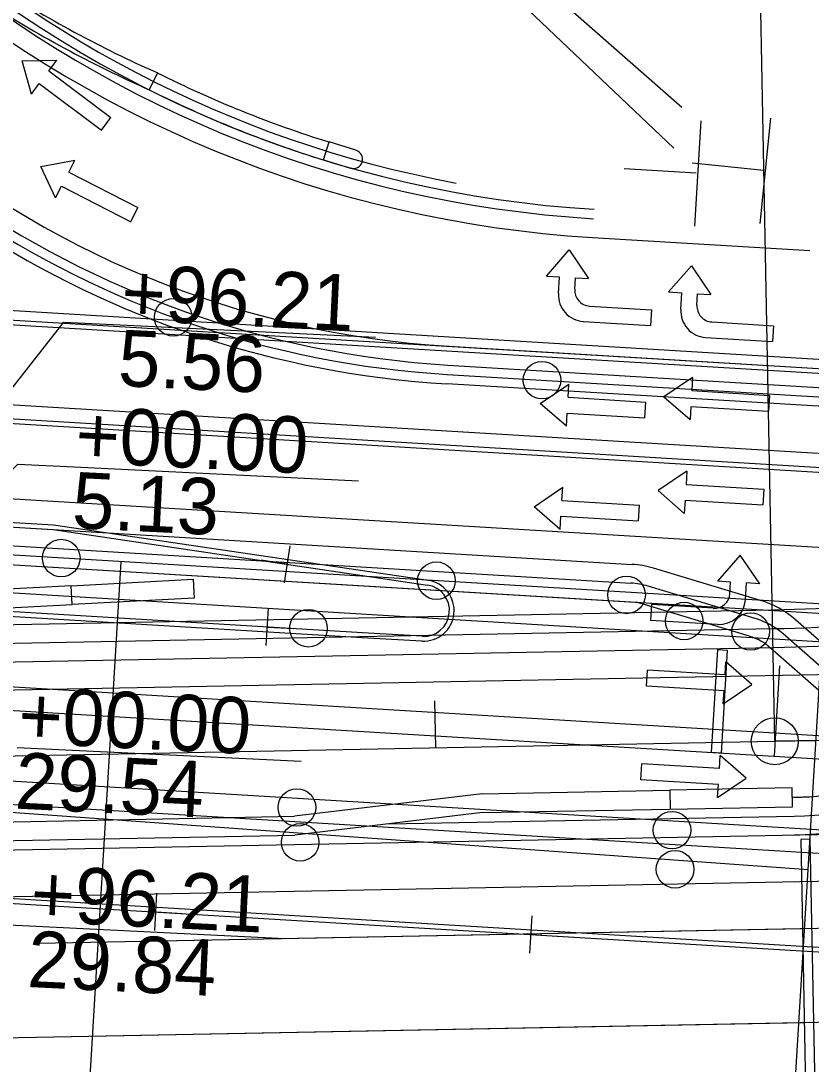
# Model space of a CAD drawing. Extents: x 659657 to 668193, y 633084 to 648639.
# Drawn here: x 662595.7 to 662679.8, y 642371.9 to 642483 of the extents above; entities that cross this region are included whole.
import ezdxf

# ---------------------------------------------------------------- set-up
doc = ezdxf.new("R2010")
doc.units = 0
for name, color, linetype in [('R_Draft', 7, 'Continuous'), ('R_MOT_Stage 1', 7, 'Continuous'), ('R_MOT_Stage 1_Striping', 7, 'Continuous'), ('R_MOT_Stage 1B', 7, 'Continuous'), ('R_MOT_Stage 1B_Striping', 7, 'Continuous'), ('R_MOT_Stage 2', 7, 'Continuous'), ('R_MOT_Stage 2_Striping', 7, 'Continuous'), ('R_MOT_Stage 3', 7, 'Continuous'), ('R_MOT_Stage 3_Striping', 7, 'Continuous'), ('R_MOT_Stage 4', 7, 'Continuous'), ('R_MOT_STAGE 4_ALG', 7, 'Continuous'), ('R_MOT_Stage 4_Striping', 7, 'Continuous'), ('R_MOT_Stage 5', 7, 'Continuous'), ('R_MOT_Stage 5_Striping', 7, 'Continuous'), ('R_MOT_Stage 5_Striping_PPM', 7, 'Continuous'), ('T_SIGNAL CONTROL CABINET', 7, 'Continuous'), ('TEMP_DETECTION ZONE_Stage 2', 7, 'Continuous'), ('TEMP_SIGNAL_HEAD_STAGE 2', 7, 'Continuous'), ('TEXT_TEMP_SIGNAL_POLES_STAGE 2', 7, 'Continuous')]:
    doc.layers.add(name, color=color, linetype=linetype)

msp = doc.modelspace()

# ---------------------------------------------------------------- linework, layer by layer
for p, q in [((662606.31, 642450.61), (662633.48, 642449.29)), ((662601.41, 642435.46), (662631.66, 642433.99)), ((662472.14, 642402.33), (662675.98, 642406.25)), ((662595.34, 642405.58), (662625.58, 642404.12)), ((662596.66, 642386.58), (662623.83, 642385.26))]:
    msp.add_line(p, q)
for points in [[(662577.3, 642421.56), (662600.32, 642450.9), (662606.31, 642450.61)], [(662581.11, 642421.76), (662595.42, 642435.75), (662601.41, 642435.46)], [(662575.84, 642397.32), (662590.67, 642386.87), (662596.66, 642386.58)]]:
    msp.add_lwpolyline(points)
msp.add_arc((662690.63, 641644.39), 762, 88.24549, 91.10143)
at = {"layer": 'R_Draft'}
for p, q in [((662607.84, 642523.97), (662665.24, 642469.4)), ((662675.54, 642472.59), (662674.4, 642461.4)), ((662674.81, 642467.04), (662667.17, 642467.82))]:
    msp.add_line(p, q, dxfattribs=at)
at = {"layer": 'R_MOT_Stage 1'}
for centre in [(662625.46, 642395.49), (662665.36, 642392.62)]:
    msp.add_circle(centre, 2, dxfattribs=at)
at = {"layer": 'R_MOT_Stage 1_Striping'}
msp.add_lwpolyline([(662365.81, 642413.1), (662545.74, 642402.23), (662679.56, 642392.6)], dxfattribs=at)
at = {"layer": 'R_MOT_Stage 1B'}
for p, q in [((662609.4, 642475.63), (662610.3, 642477.42)), ((662627.93, 642468.17), (662628.53, 642470.08)), ((662631.39, 642469.19), (662628.53, 642470.08)), ((662627.93, 642468.17), (662630.8, 642467.28))]:
    msp.add_line(p, q, dxfattribs=at)
for centre, radius, start, end in [((662664.1, 642584.68), 121, 191.5452, 259.5087), ((662664.1, 642584.68), 123, 191.5452, 266.5452), ((662658.88, 642587.86), 120.65, 236.8623, 246.2551), ((662658.88, 642587.86), 122.65, 236.8152, 246.208), ((662664.1, 642584.68), 120, 243.3636, 252.7563), ((662664.1, 642584.68), 122, 243.3636, 252.7564), ((662631.1, 642468.23), 1, 252.7573, 72.7573)]:
    msp.add_arc(centre, radius, start, end, dxfattribs=at)
at = {"layer": 'R_MOT_Stage 1B_Striping'}
msp.add_line((662656.57, 642459.91), (662679.72, 642458.51), dxfattribs=at)
msp.add_arc((662664.1, 642584.68), 125, 191.5452, 266.5452, dxfattribs=at)
at = {"layer": 'R_MOT_Stage 2'}
for centre in [(662625.12, 642399.2), (662665.04, 642396.79)]:
    msp.add_circle(centre, 2, dxfattribs=at)
at = {"layer": 'R_MOT_Stage 2_Striping'}
for p, q in [((662564.68, 642453.94), (662717.74, 642444.7)), ((662586.38, 642442.61), (662717.14, 642434.71)), ((662585.77, 642432.63), (662697.57, 642425.88)), ((662585.17, 642422.65), (662696.97, 642415.9)), ((662584.57, 642412.66), (662696.36, 642405.91))]:
    msp.add_line(p, q, dxfattribs=at)
msp.add_lwpolyline([(662544.65, 642404.55), (662583.97, 642402.68), (662695.76, 642395.93)], dxfattribs=at)
at = {"layer": 'R_MOT_Stage 3'}
for p, q in [((662532.02, 642430.86), (662660.67, 642423.1)), ((662531.97, 642428.86), (662661.25, 642421.06)), ((662673.88, 642419.34), (662662.5, 642422.77)), ((662673.3, 642417.43), (662661.25, 642421.06)), ((662694.99, 642401.73), (662676.86, 642417.69)), ((662691.12, 642402.46), (662675.54, 642416.18)), ((662644.83, 642400.65), (662624.87, 642398.26)), ((662644.83, 642400.65), (662664.82, 642401.03)), ((662497.17, 642395.81), (662624.87, 642398.26)), ((662644.86, 642398.65), (662624.91, 642396.26)), ((662634.88, 642397.46), (662678.04, 642398.28)), ((662644.86, 642398.65), (662664.86, 642399.03)), ((662497.13, 642393.81), (662624.91, 642396.26))]:
    msp.add_line(p, q, dxfattribs=at)
msp.add_lwpolyline([(662664.86, 642399.03), (662677.86, 642399.28), (662677.82, 642401.28), (662664.82, 642401.03)], close=True, dxfattribs=at)
for centre in [(662600.03, 642425.76), (662639.96, 642423.35), (662660.2, 642421.84), (662673.41, 642417.94)]:
    msp.add_circle(centre, 2, dxfattribs=at)
for centre, radius, start, end in [((662660.19, 642415.11), 8, 73.2256, 86.5452), ((662671.57, 642411.68), 8, 48.6396, 73.2256), ((662671.57, 642411.68), 6, 48.6396, 73.2256), ((662677.12, 642446.28), 46, 271.1014, 287.7285), ((662677.12, 642446.28), 48, 271.1014, 291.8551)]:
    msp.add_arc(centre, radius, start, end, dxfattribs=at)
at = {"layer": 'R_MOT_Stage 3_Striping'}
for p, q in [((662582.93, 642451.83), (662717.68, 642443.7)), ((662582.26, 642440.85), (662852.85, 642424.52)), ((662581.6, 642429.87), (662660.79, 642425.09)), ((662674.46, 642421.26), (662663.08, 642424.69)), ((662696.31, 642403.23), (662678.18, 642419.19)), ((662471.94, 642392.32), (662695.17, 642396.61)), ((662597.59, 642384.74), (662695.36, 642386.62)), ((662597.39, 642374.73), (662695.55, 642376.62))]:
    msp.add_line(p, q, dxfattribs=at)
for centre, radius, start, end in [((662660.19, 642415.11), 10, 73.2256, 86.5452), ((662671.57, 642411.68), 10, 48.6396, 73.2256), ((662677.12, 642446.28), 50, 271.1014, 291.8551), ((662582.74, 643136.59), 762, 266.54523, 271.10143)]:
    msp.add_arc(centre, radius, start, end, dxfattribs=at)
at = {"layer": 'R_MOT_Stage 4'}
for p, q in [((662641.18, 642446.31), (662707.9, 642442.29)), ((662707.78, 642440.29), (662641.06, 642444.32)), ((662541.55, 642417.66), (662675.77, 642420.25)), ((662479.84, 642414.48), (662675.81, 642418.25))]:
    msp.add_line(p, q, dxfattribs=at)
for points in [[(662480.71, 642414.45), (662601.2, 642420.82), (662601.1, 642422.81), (662480.61, 642416.45)], [(662601.2, 642420.82), (662601.1, 642422.81), (662614.08, 642423.5), (662614.18, 642421.5)]]:
    msp.add_lwpolyline(points, close=True, dxfattribs=at)
for centre in [(662611.95, 642451.4), (662651.2, 642444.71), (662666.33, 642419.06), (662626.34, 642418.29)]:
    msp.add_circle(centre, 2, dxfattribs=at)
for centre, radius, start, end in [((662647.33, 642548.13), 102, 202.9101, 266.5452), ((662647.33, 642548.13), 104, 207.4876, 266.5452), ((662672, 642616.21), 196, 271.1014, 281.9222), ((662672, 642616.21), 198, 271.1014, 281.9222)]:
    msp.add_arc(centre, radius, start, end, dxfattribs=at)
at = {"layer": 'R_MOT_STAGE 4_ALG'}
for p, q in [((662472.14, 642402.33), (662675.98, 642406.25)), ((662675.98, 642406.25), (662694.97, 642406.61))]:
    msp.add_line(p, q, dxfattribs=at)
for points in [[(662675.98, 642406.25), (662672.14, 642606.21)], [(662639.75, 642410.55), (662639.85, 642405.55)]]:
    msp.add_lwpolyline(points, dxfattribs=at)
msp.add_circle((662675.98, 642406.25), 2.5, dxfattribs=at)
msp.add_arc((662690.63, 641644.39), 762, 88.24549, 91.10143, dxfattribs=at)
at = {"layer": 'R_MOT_Stage 4_Striping'}
for p, q in [((662641.3, 642448.31), (662708.02, 642444.28)), ((662472.35, 642412.33), (662675.84, 642416.25)), ((662472.14, 642402.33), (662675.98, 642406.25)), ((662471.94, 642392.32), (662695.17, 642396.61)), ((662679.75, 642395.82), (662678.75, 642395.8)), ((662678.75, 642395.8), (662679.32, 642366.3)), ((662680.32, 642366.33), (662679.75, 642395.82)), ((662597.59, 642384.74), (662678.94, 642386.3)), ((662597.39, 642374.73), (662679.13, 642376.3))]:
    msp.add_line(p, q, dxfattribs=at)
for centre, radius, start, end in [((662647.33, 642548.13), 100, 191.5452, 266.5452), ((662672, 642616.21), 200, 271.1014, 281.9222), ((662690.63, 641644.39), 762, 88.24549, 91.10143), ((662582.74, 643136.59), 762, 266.54523, 271.10143)]:
    msp.add_arc(centre, radius, start, end, dxfattribs=at)
at = {"layer": 'R_MOT_Stage 5'}
for p, q in [((662624.35, 642427.07), (662623.77, 642423.14)), ((662624, 642425.12), (662621.32, 642425.52)), ((662621.85, 642416.44), (662622.09, 642420.42)), ((662622.03, 642418.42), (662624.74, 642418.25)), ((662609.98, 642386.1), (662610.22, 642390.08)), ((662610.16, 642388.08), (662612.87, 642387.91)), ((662649.91, 642383.69), (662650.15, 642387.67)), ((662650.09, 642385.67), (662652.8, 642385.5))]:
    msp.add_line(p, q, dxfattribs=at)
at = {"layer": 'R_MOT_Stage 5_Striping'}
for p, q in [((661919.1, 642491.41), (662682.71, 642445.31)), ((661918.5, 642481.43), (662682.11, 642435.33)), ((662431.9, 642439.41), (662599.22, 642429.31)), ((662599.22, 642429.31), (662639.08, 642423.39)), ((662523.51, 642423.86), (662632.67, 642417.27)), ((662632.67, 642417.27), (662638.4, 642416.93)), ((662520.53, 642414.02), (662705.2, 642402.88)), ((662410.13, 642410.67), (662704.6, 642392.89)), ((662409.53, 642400.69), (662713.96, 642382.31))]:
    msp.add_line(p, q, dxfattribs=at)
msp.add_lwpolyline([(662670.92, 642415.97), (662670.26, 642404.99), (662669.26, 642405.05), (662669.93, 642416.03)], close=True, dxfattribs=at)
msp.add_arc((662638.6, 642420.17), 3.25, 266.5452, 81.5452, dxfattribs=at)
at = {"layer": 'R_MOT_Stage 5_Striping_PPM'}
for radius, end in [(238.73, 86.5452), (253.73, 62.8692)]:
    msp.add_arc((662357.6, 642147.63), radius, 156.1234, end, dxfattribs=at)
at = {"layer": 'T_SIGNAL CONTROL CABINET'}
for p, q in [((662595.86, 642478.73), (662599.55, 642478.78)), ((662595.86, 642478.73), (662599.55, 642478.78)), ((662596.85, 642475.18), (662595.86, 642478.73)), ((662596.85, 642475.18), (662595.86, 642478.73)), ((662598.7, 642477.65), (662599.55, 642478.78)), ((662598.7, 642477.65), (662599.55, 642478.78)), ((662598.7, 642477.65), (662605.32, 642472.68)), ((662598.7, 642477.65), (662605.32, 642472.68)), ((662596.85, 642475.18), (662597.69, 642476.3)), ((662596.85, 642475.18), (662597.69, 642476.3)), ((662597.69, 642476.3), (662604.3, 642471.33)), ((662597.69, 642476.3), (662604.3, 642471.33)), ((662604.3, 642471.33), (662605.32, 642472.68)), ((662604.3, 642471.33), (662605.32, 642472.68)), ((662678.22, 642370.94), (662684.25, 642470.76)), ((662597.85, 642467.45), (662601.48, 642468.12)), ((662599.42, 642464.11), (662597.85, 642467.45)), ((662600.83, 642466.87), (662601.48, 642468.12)), ((662600.83, 642466.87), (662608.19, 642463.08)), ((662599.42, 642464.11), (662600.06, 642465.37)), ((662600.06, 642465.37), (662607.42, 642461.58)), ((662607.42, 642461.58), (662608.19, 642463.08)), ((662651.67, 642455.79), (662654.09, 642458.57)), ((662654.09, 642458.57), (662656.16, 642455.52)), ((662664.68, 642454.1), (662667.1, 642456.88)), ((662667.1, 642456.88), (662669.17, 642453.83)), ((662651.67, 642455.79), (662653.07, 642455.71)), ((662652.96, 642453.93), (662653.07, 642455.71)), ((662654.68, 642454.39), (662654.76, 642455.61)), ((662654.76, 642455.61), (662656.16, 642455.52)), ((662664.68, 642454.1), (662666.08, 642454.01)), ((662665.97, 642452.24), (662666.08, 642454.01)), ((662667.69, 642452.7), (662667.77, 642453.91)), ((662667.77, 642453.91), (662669.17, 642453.83)), ((662656.26, 642452.6), (662662.84, 642452.21)), ((662662.84, 642452.21), (662662.74, 642450.52)), ((662655.6, 642450.95), (662662.74, 642450.52)), ((662669.28, 642450.91), (662675.85, 642450.51)), ((662675.85, 642450.51), (662675.75, 642448.83)), ((662668.61, 642449.26), (662675.75, 642448.83)), ((662641.12, 642445.32), (662740.31, 642439.33)), ((662667.23, 642444.99), (662664.18, 642442.92)), ((662667.23, 642444.99), (662667.14, 642443.59)), ((662651.02, 642442.21), (662654.07, 642444.28)), ((662653.99, 642442.88), (662654.07, 642444.28)), ((662653.99, 642442.88), (662662.25, 642442.38)), ((662664.18, 642442.92), (662666.96, 642440.5)), ((662667.14, 642443.59), (662675.4, 642443.09)), ((662675.4, 642443.09), (662675.3, 642441.4)), ((662653.8, 642439.79), (662651.02, 642442.21)), ((662662.15, 642440.7), (662662.25, 642442.38)), ((662667.04, 642441.9), (662666.96, 642440.5)), ((662667.04, 642441.9), (662675.3, 642441.4)), ((662653.8, 642439.79), (662653.89, 642441.19)), ((662653.89, 642441.19), (662662.15, 642440.7)), ((662431.88, 642438.91), (662599.16, 642428.81)), ((662666.63, 642435.01), (662663.57, 642432.94)), ((662666.63, 642435.01), (662666.54, 642433.61)), ((662650.36, 642431.23), (662653.41, 642433.3)), ((662653.32, 642431.9), (662653.41, 642433.3)), ((662663.57, 642432.94), (662666.35, 642430.52)), ((662666.54, 642433.61), (662674.8, 642433.11)), ((662674.8, 642433.11), (662674.7, 642431.42)), ((662653.32, 642431.9), (662661.58, 642431.4)), ((662666.44, 642431.92), (662666.35, 642430.52)), ((662666.44, 642431.92), (662674.7, 642431.42)), ((662653.14, 642428.81), (662650.36, 642431.23)), ((662661.48, 642429.72), (662661.58, 642431.4)), ((662852, 642410.54), (662532, 642429.86)), ((662653.14, 642428.81), (662653.22, 642430.21)), ((662653.22, 642430.21), (662661.48, 642429.72)), ((662531.97, 642428.86), (662721.67, 642417.41)), ((662599.16, 642428.81), (662639.01, 642422.89)), ((662672.3, 642426.07), (662669.87, 642423.29)), ((662674.37, 642423.02), (662672.3, 642426.07)), ((662606.37, 642425.37), (662600.35, 642325.55)), ((662632.7, 642417.77), (662523.53, 642424.36)), ((662671.28, 642423.21), (662669.87, 642423.29)), ((662671.2, 642421.99), (662671.28, 642423.21)), ((662672.85, 642421.33), (662672.96, 642423.11)), ((662674.37, 642423.02), (662672.96, 642423.11)), ((662662.84, 642420.81), (662662.74, 642419.12)), ((662669.42, 642420.41), (662662.84, 642420.81)), ((662669.88, 642418.69), (662662.74, 642419.12)), ((662638.43, 642417.43), (662632.7, 642417.77)), ((662706.82, 642413.84), (662580.43, 642411.41)), ((662662.32, 642412.13), (662662.42, 642413.82)), ((662670.68, 642413.32), (662662.42, 642413.82)), ((662670.68, 642413.32), (662670.77, 642414.72)), ((662673.55, 642412.3), (662670.77, 642414.72)), ((662676.48, 642414.27), (662675.9, 642404.65)), ((662670.58, 642411.63), (662662.32, 642412.13)), ((662670.49, 642410.23), (662673.55, 642412.3)), ((662670.49, 642410.23), (662670.58, 642411.63)), ((662661.72, 642402.15), (662661.82, 642403.84)), ((662670.08, 642403.34), (662661.82, 642403.84)), ((662670.08, 642403.34), (662670.16, 642404.74)), ((662672.94, 642402.32), (662670.16, 642404.74)), ((662669.98, 642401.65), (662661.72, 642402.15)), ((662669.89, 642400.25), (662672.94, 642402.32)), ((662669.89, 642400.25), (662669.98, 642401.65)), ((662409.51, 642400.19), (662713.92, 642381.81)), ((663079.28, 642399), (662579.98, 642389.4))]:
    msp.add_line(p, q, dxfattribs=at)
for centre, radius, start, end in [((662664.1, 642584.68), 122, 191.5452, 266.5452), ((662647.33, 642548.13), 103, 205.4077, 266.5452), ((662655.77, 642453.76), 2.81, 176.5452, 266.5452), ((662656.37, 642454.29), 1.69, 176.5452, 266.5452), ((662669.38, 642452.59), 1.69, 176.5452, 266.5452), ((662668.78, 642452.07), 2.81, 176.5452, 266.5452), ((662638.6, 642420.17), 2.75, 266.5452, 81.5452), ((662669.52, 642422.09), 1.69, 266.5452, 356.5452), ((662670.05, 642421.5), 2.81, 266.5452, 356.5452), ((662677.12, 642446.28), 46, 270.8991, 293.2467)]:
    msp.add_arc(centre, radius, start, end, dxfattribs=at)
at = {"layer": 'TEMP_DETECTION ZONE_Stage 2'}
for p, q in [((662607.84, 642523.97), (662665.24, 642469.4)), ((662675.54, 642472.59), (662674.4, 642461.4)), ((662674.81, 642467.04), (662667.17, 642467.82))]:
    msp.add_line(p, q, dxfattribs=at)
at = {"layer": 'TEMP_SIGNAL_HEAD_STAGE 2'}
for p, q in [((662607.84, 642523.97), (662665.24, 642469.4)), ((662675.54, 642472.59), (662674.4, 642461.4)), ((662674.81, 642467.04), (662667.17, 642467.82))]:
    msp.add_line(p, q, dxfattribs=at)
at = {"layer": 'TEXT_TEMP_SIGNAL_POLES_STAGE 2'}
for p, q in [((662603.19, 642529.11), (662666.07, 642473.79)), ((662668.11, 642472.33), (662667.43, 642461.11)), ((662667.61, 642466.76), (662659.94, 642467.22))]:
    msp.add_line(p, q, dxfattribs=at)

# ---------------------------------------------------------------- texts
for s, p in [('+96.21', (662606.33, 642451.11)), ('5.56', (662606, 642444.11)), ('+00.00', (662601.44, 642435.96)), ('5.13', (662601.1, 642428.96)), ('+00.00', (662595.36, 642406.08)), ('29.54', (662595.02, 642399.09)), ('+96.21', (662596.68, 642387.08)), ('29.84', (662596.34, 642380.09))]:
    msp.add_text(s, height=6, rotation=357.2199).set_placement(p)

doc.saveas('drawing.dxf')
